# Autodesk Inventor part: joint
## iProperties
Shininess: 64.0
Length Units: 11269
Angle Units: 11279
Time Units: 11290
Mass Units: 11283
Length Display Precision: 3
Angle Display Precision: 2
Compacted: True
Part Number: joint
Document SubType Name: Modeling
Created: 2005-01
Material: Par défaut
Designer: David
Manufacturer: Standard
Standards Organization: Custom
Density: 0.0
Volumn: 0.0
Area: 0.0
PropertySet Name: Model Information
Control State: 0
Master: False
Checked Out: False
Author: David
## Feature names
1. Révolution1 [Revolution]
